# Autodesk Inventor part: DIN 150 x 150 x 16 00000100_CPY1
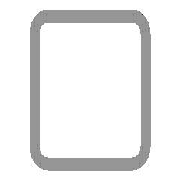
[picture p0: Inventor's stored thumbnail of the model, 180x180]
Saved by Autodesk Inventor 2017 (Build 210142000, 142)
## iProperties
Created: 2016-02
Part Number: DIN 150 x 150 x 16 00000100_CPY1
Material: Steel, Mild
Description: Cold formed welded structural hollow sections of non-alloy and fine grain structural steel
Document SubType Name: Modeling
Standard: DIN
Designer: iusti
Standard Revision: 2006-07
Standards Organization: DIN
Language: en-US
Size Designation: 150 x 150 x 16
Categories: <MemberInstance><Categories><Category DisplayName="Structural Shapes" InternalName="089c4875-fa83-4c05-b084-43b9cc11f5ed" Mnemonic="GRDR"><CategoryParameter Dis
Stock Number: 150 x 150 x 16
Mass: 301820 g
Surface Area: 48238.1 cm^2
Volume: 38448.4 cm^3
Density: 7.85 g/cm^3
Appearance: Semi-Polished
IsCustomPart: 1
G_W: 150.000 mm
G_H: 150.000 mm
G_L: 5233.011 mm
+A8523F61-15A1-41A4-8D30-2D7D9D924B11+CUTDETAIL2: Cut
+987C6673-447C-412A-9B24-0CD20188E66E+CUTDETAIL3: Miter 69.88 deg
_CCFamilyMember: 76
_CCFamilyDisplayName: DIN EN 10219-2 (Square Hollow Section - Cold Formed) - Cold formed welded structural hollow sections of non-alloy and fine grain structural steel
_FrameMemberDoc: Frame Member File
_Version: 15.0.0
_GetPNFromCC: 1
Author: iusti
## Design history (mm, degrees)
node "Start plane"
node "End plane"
sketch "Sketch"
  geometry: L1 (-75, -27)-(-75, 27); L2 (-27, 75)-(27, 75); L3 (75, 27)-(75, -27); L4 (27, -75)-(-27, -75); L5 (-27, 59)-(27, 59); L6 (59, 27)-(59, -27); L7 (27, -59)-(-27, -59); L8 (-59, -27)-(-59, 27); L9 (0, 118.918)-(0, -118.918) reference; L10 (-118.918, 0)-(118.918, 0) reference; A1 r 48 centre (-27, -27) between (-75, -27) and (-27, -75); A2 r 48 centre (-27, 27) between (-27, 75) and (-75, 27); A3 r 48 centre (27, 27) between (75, 27) and (27, 75); A4 r 48 centre (27, -27) between (27, -75) and (75, -27); A5 r 32 centre (-27, 27) between (-27, 59) and (-59, 27); A6 r 32 centre (27, 27) between (59, 27) and (27, 59); A7 r 32 centre (27, -27) between (27, -59) and (59, -27); A8 r 32 centre (-27, -27) between (-59, -27) and (-27, -59)
  constraints: 16 end point, 16 point on circle, 8 centre point, 8 tangent, 4 parallel, 3 equal radius, 2 perpendicular, 7 other
  dimensions: "d7" = 48 radius of A1 (= G_IR); "d10" = 150 distance between parallel lines of L2 L4 (= G_H); "d11" = 150 distance between parallel lines of L1 L3 (= G_W); "d12" = 16 distance between parallel lines of L3 L6 (= G_T); "d15" = 75 distance between parallel lines of L2 L10 (= 0.5 x d10); "d16" = 75 distance between parallel lines of L9 L3 (= 0.5 x d11)
extrude "Body" new body sketch "Sketch" stored distance "d3" = 5233.01077 (= G_L); taper "d4" = 0 deg
node "Driven Length"
  sketch "Sketch3"
    geometry: L1 (0, 0)-(10, 0) reference
    constraints: 2 end point, 1 horizontal
  workplane "Work Plane3"
  sketch "Sketch4"
    geometry: L1 (-2, 34.78)-(12, 34.78) reference; L2 (-2, 5267.791)-(12, 5267.791) reference
    dimensions: "d18" = 5233.01077 distance between parallel lines of L1 L2 (derived)
workplane "Work Plane5"
split "Split2"
workplane "Work Plane6"
split "Split3"
body "Solid1"
other parameters: "G_W" = 150 [user parameter; used in 1 equation term], "G_H" = 150 [user parameter; used in 1 equation term], "G_T" = 16 [user parameter; used in 1 equation term], "G_IR" = 48 [user parameter; used in 1 equation term], "G_L" = 5233.01077 (= d18) [user parameter; used in 1 equation term], "G_OFFSET_START" = -34.77977 [user parameter; used in 1 equation term], "G_OFFSET_END" = 27.4779 [user parameter; used in 1 equation term], "d13" = 34.77977 (= -G_OFFSET_START), "d14" = 5267.79054 (= G_OFFSET_END + B_L), "B_L" = 5240.31264 [user parameter; used in 1 equation term], "d17" = 90 deg
